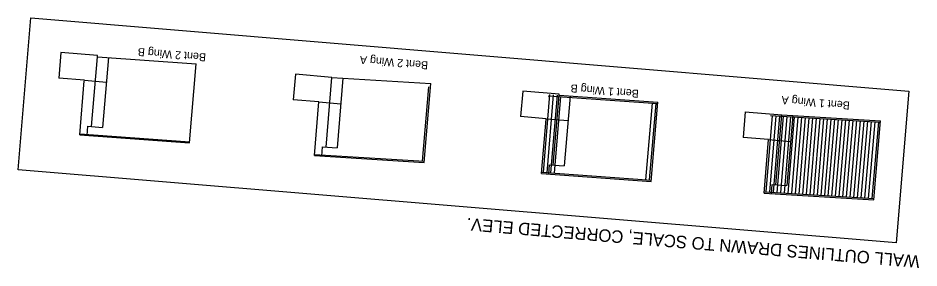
# Model space of a CAD drawing. Extents: x 1313815 to 1314857, y 2089008 to 2089414.
# Drawn here: x 1314183.7 to 1314306.5, y 2089220.6 to 2089254.8 of the extents above; entities that cross this region are included whole.
import ezdxf

# ---------------------------------------------------------------- set-up
doc = ezdxf.new("R2010")
doc.units = 0
for name, color, linetype in [('B-Gen-Construction Line', 7, 'Continuous'), ('B-Gen-Hidden', 7, 'Continuous'), ('B-Gen-Rebar', 7, 'Continuous'), ('B-Gen-Viewport', 7, 'Continuous'), ('B-Sub-Abutment Cap (Hidden)', 7, 'Continuous'), ('B-Sub-Wingwall', 7, 'Continuous')]:
    doc.layers.add(name, color=color, linetype=linetype)

msp = doc.modelspace()

# ---------------------------------------------------------------- linework, layer by layer
at = {"layer": 'B-Gen-Construction Line'}
for p, q in [((1314255.95, 2089244.14), (1314270.91, 2089243.07)), ((1314286.28, 2089241.46), (1314301.26, 2089240.54)), ((1314192.14, 2089238.95), (1314207.1, 2089237.86)), ((1314224.11, 2089236.13), (1314239.09, 2089235.19)), ((1314255.07, 2089233.68), (1314270.04, 2089232.61)), ((1314285.41, 2089231), (1314300.38, 2089230.08))]:
    msp.add_line(p, q, dxfattribs=at)
at = {"layer": 'B-Gen-Hidden'}
for p, q in [((1314196.02, 2089249.36), (1314195.22, 2089239.82)), ((1314227.99, 2089246.56), (1314227.2, 2089237.02)), ((1314258.95, 2089244.09), (1314258.16, 2089234.55)), ((1314289.29, 2089241.42), (1314288.49, 2089231.89)), ((1314193.12, 2089238.71), (1314193.23, 2089239.97)), ((1314193.23, 2089239.97), (1314195.22, 2089239.82)), ((1314192.12, 2089238.79), (1314207.08, 2089237.7)), ((1314225.1, 2089235.9), (1314225.2, 2089237.15)), ((1314225.2, 2089237.15), (1314227.2, 2089237.02)), ((1314224.1, 2089235.97), (1314239.07, 2089235.03)), ((1314256.06, 2089233.44), (1314256.16, 2089234.7)), ((1314256.06, 2089233.45), (1314256.16, 2089234.68)), ((1314256.16, 2089234.7), (1314258.16, 2089234.55)), ((1314255.06, 2089233.51), (1314270.02, 2089232.44)), ((1314286.39, 2089230.77), (1314286.5, 2089232.01)), ((1314286.39, 2089230.77), (1314286.5, 2089232)), ((1314286.5, 2089232.01), (1314288.49, 2089231.89)), ((1314285.39, 2089230.83), (1314300.37, 2089229.91))]:
    msp.add_line(p, q, dxfattribs=at)
at = {"layer": 'B-Gen-Rebar'}
for p, q in [((1314238.84, 2089235.21), (1314239.68, 2089245.35)), ((1314255.32, 2089233.66), (1314256.21, 2089244.29)), ((1314255.82, 2089233.63), (1314256.71, 2089244.25)), ((1314256.32, 2089233.59), (1314257.21, 2089244.22)), ((1314256.82, 2089233.55), (1314257.69, 2089244.02)), ((1314269.29, 2089232.66), (1314270.16, 2089243.13)), ((1314269.79, 2089232.63), (1314270.66, 2089243.09)), ((1314285.66, 2089231), (1314286.53, 2089241.45)), ((1314286.16, 2089230.96), (1314287.03, 2089241.41)), ((1314286.66, 2089230.92), (1314287.53, 2089241.38)), ((1314287.16, 2089230.89), (1314288.03, 2089241.35)), ((1314287.66, 2089230.86), (1314288.53, 2089241.32)), ((1314288.15, 2089230.83), (1314289.03, 2089241.29)), ((1314288.65, 2089230.8), (1314289.53, 2089241.26)), ((1314289.15, 2089230.77), (1314290.03, 2089241.23)), ((1314289.65, 2089230.74), (1314290.53, 2089241.2)), ((1314290.15, 2089230.7), (1314291.02, 2089241.17)), ((1314290.65, 2089230.67), (1314291.52, 2089241.14)), ((1314291.15, 2089230.64), (1314292.02, 2089241.11)), ((1314291.65, 2089230.61), (1314292.52, 2089241.08)), ((1314292.15, 2089230.58), (1314293.02, 2089241.05)), ((1314292.65, 2089230.55), (1314293.52, 2089241.02)), ((1314293.15, 2089230.52), (1314294.02, 2089240.98)), ((1314293.65, 2089230.49), (1314294.52, 2089240.95)), ((1314294.14, 2089230.46), (1314295.02, 2089240.92)), ((1314294.64, 2089230.43), (1314295.52, 2089240.89)), ((1314295.14, 2089230.4), (1314296.02, 2089240.86)), ((1314295.64, 2089230.37), (1314296.52, 2089240.83)), ((1314296.14, 2089230.34), (1314297.01, 2089240.8)), ((1314296.64, 2089230.31), (1314297.51, 2089240.77)), ((1314297.14, 2089230.28), (1314298.01, 2089240.74)), ((1314297.64, 2089230.25), (1314298.51, 2089240.71)), ((1314298.14, 2089230.21), (1314299.01, 2089240.68)), ((1314298.64, 2089230.18), (1314299.51, 2089240.65)), ((1314299.14, 2089230.15), (1314300.01, 2089240.62)), ((1314299.64, 2089230.12), (1314300.51, 2089240.59)), ((1314300.13, 2089230.09), (1314301.01, 2089240.56))]:
    msp.add_line(p, q, dxfattribs=at)
at = {"layer": 'B-Gen-Viewport'}
msp.add_lwpolyline([(1314303.41, 2089224.05), (1314183.7, 2089234.04), (1314185.43, 2089254.76), (1314305.14, 2089244.77)], close=True, dxfattribs=at)
at = {"layer": 'B-Sub-Abutment Cap (Hidden)'}
for p, q in [((1314193.72, 2089239.93), (1314194.52, 2089249.47)), ((1314192.75, 2089246.26), (1314195.74, 2089246.01)), ((1314225.7, 2089237.11), (1314226.49, 2089246.65)), ((1314256.66, 2089234.66), (1314257.46, 2089244.2)), ((1314224.71, 2089243.29), (1314227.7, 2089243.04)), ((1314287, 2089231.98), (1314287.79, 2089241.51)), ((1314255.68, 2089241), (1314258.67, 2089240.75)), ((1314286.01, 2089238.14), (1314289, 2089237.89))]:
    msp.add_line(p, q, dxfattribs=at)
at = {"layer": 'B-Sub-Wingwall'}
for p, q in [((1314189.55, 2089250.04), (1314189.26, 2089246.55)), ((1314194.53, 2089249.62), (1314189.55, 2089250.04)), ((1314194.52, 2089249.47), (1314194.53, 2089249.62)), ((1314194.52, 2089249.47), (1314207.99, 2089248.49)), ((1314207.08, 2089237.7), (1314207.99, 2089248.49)), ((1314192.75, 2089246.26), (1314189.26, 2089246.55)), ((1314192.12, 2089238.79), (1314192.74, 2089246.19)), ((1314221.51, 2089247.07), (1314221.22, 2089243.58)), ((1314226.49, 2089246.65), (1314221.51, 2089247.07)), ((1314226.49, 2089246.65), (1314239.97, 2089245.82)), ((1314239.07, 2089235.03), (1314239.97, 2089245.82)), ((1314252.49, 2089244.78), (1314252.2, 2089241.29)), ((1314257.47, 2089244.36), (1314252.49, 2089244.78)), ((1314224.71, 2089243.29), (1314221.22, 2089243.58)), ((1314257.46, 2089244.2), (1314257.47, 2089244.36)), ((1314257.46, 2089244.2), (1314270.92, 2089243.24)), ((1314224.1, 2089235.97), (1314224.71, 2089243.29)), ((1314270.02, 2089232.44), (1314270.92, 2089243.24)), ((1314255.68, 2089241), (1314252.2, 2089241.29)), ((1314282.81, 2089241.92), (1314282.52, 2089238.44)), ((1314282.81, 2089241.92), (1314287.79, 2089241.51)), ((1314287.79, 2089241.51), (1314301.27, 2089240.71)), ((1314255.06, 2089233.51), (1314255.68, 2089240.93)), ((1314300.37, 2089229.91), (1314301.27, 2089240.71)), ((1314286.01, 2089238.14), (1314282.52, 2089238.44)), ((1314285.39, 2089230.83), (1314286.01, 2089238.14))]:
    msp.add_line(p, q, dxfattribs=at)

# ---------------------------------------------------------------- texts
at = {"layer": 'B-Gen-Construction Line'}
msp.add_text('WALL OUTLINES DRAWN TO SCALE, CORRECTED ELEV. ', height=1.6984, rotation=175.2284, dxfattribs=at).set_placement((1314306.65, 2089222.3))
at = {"layer": 'B-Sub-Abutment Cap (Hidden)'}
for s, p in [('Bent 2 Wing B', (1314209.36, 2089249.9)), ('Bent 2 Wing A', (1314239.63, 2089248.81)), ('Bent 1 Wing B', (1314268.35, 2089244.93)), ('Bent 1 Wing A', (1314297.11, 2089243.32))]:
    msp.add_text(s, height=1.0911, rotation=175.2284, dxfattribs=at).set_placement(p)

doc.saveas('drawing.dxf')
